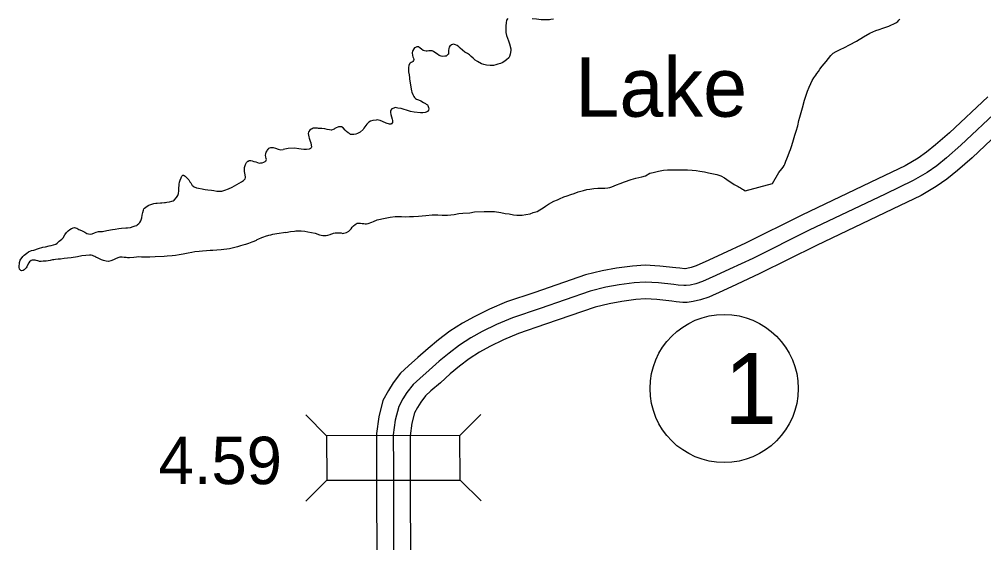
# Model space of a CAD drawing. Extents: x 31699 to 244310, y -8841 to 11474.
# Drawn here: x 101516 to 102088, y 3394 to 3705 of the extents above; entities that cross this region are included whole.
import ezdxf

# ---------------------------------------------------------------- set-up
doc = ezdxf.new("R2010")
doc.units = 0
for name, color, linetype in [('B_Logo', 7, 'Continuous'), ('R_Border Notes', 7, 'Continuous'), ('R_Draft', 7, 'Continuous'), ('R_XS_EARTHWORK_STAGE1', 7, 'Continuous'), ('R_XS_EARTHWORK_STAGE2', 7, 'Continuous'), ('S_WALL', 7, 'Continuous')]:
    doc.layers.add(name, color=color, linetype=linetype)

msp = doc.modelspace()

# ---------------------------------------------------------------- linework, layer by layer
at = {"layer": 'B_Logo'}
msp.add_lwpolyline([(102097.66, 3651.92), (102074.84, 3630.55), (102066.33, 3623.1), (102060.59, 3618.36), (102054.9, 3614.36), (102046.56, 3609.52), (102030, 3601.51), (101984.73, 3580.02), (101951.27, 3563.33), (101937.49, 3556.96), (101929.33, 3553.19), (101921.44, 3549.63), (101917.46, 3548.25), (101914.07, 3547.47), (101911.75, 3547.11), (101910.35, 3547.16), (101906.94, 3547.46), (101904.41, 3547.76), (101895.27, 3548.79), (101887.47, 3549.24), (101880.88, 3548.76), (101871.96, 3547.66), (101863.99, 3546.16), (101854.82, 3543.85), (101825.02, 3533.63), (101808.69, 3528.09), (101799.14, 3524.04), (101790.53, 3519.8), (101783.97, 3516.19), (101777.16, 3511.83), (101770.95, 3507.09), (101765, 3502.27), (101759.13, 3496.93), (101753.53, 3492.06), (101749.57, 3488.4), (101745.89, 3483.62), (101743.54, 3479.85), (101741.05, 3475.28), (101739.01, 3467.31), (101737.84, 3458.54), (101737.86, 3438.97), (101738, 3373.37)], dxfattribs=at)
at = {"layer": 'R_Border Notes'}
msp.add_circle((101934.29, 3486.01), 44, dxfattribs=at)
at = {"layer": 'R_Draft'}
for points in [[(101805.95, 3705.89), (101805.1, 3704.75), (101804.85, 3703.21), (101804.67, 3701.53), (101804.7, 3699.6), (101804.72, 3697.52), (101805.08, 3695.66), (101806.19, 3692.6), (101806.81, 3690.8), (101807.59, 3687.74), (101807.59, 3687), (101807.41, 3685.67), (101807.22, 3684.66), (101806.91, 3683.25), (101806.45, 3682.45), (101805, 3681.16), (101804.34, 3680.61), (101802.82, 3679.72), (101801.56, 3679.11), (101799.96, 3678.68), (101798.7, 3678.2), (101797.3, 3677.98), (101795.37, 3677.95), (101793.23, 3678.06), (101791.69, 3678.44), (101790.22, 3678.96), (101787.8, 3680.19), (101786.39, 3681.04), (101785.3, 3682.23), (101784.16, 3683.22), (101783.14, 3684.21), (101781.93, 3684.99), (101780.32, 3685.84), (101778.84, 3686.96), (101777.62, 3688.14), (101776.68, 3688.93), (101775.67, 3689.72), (101774.86, 3690.24), (101773.65, 3690.56), (101772.39, 3690.15), (101771.47, 3689.46), (101771.01, 3688.86), (101770.75, 3688.05), (101770.7, 3686.78), (101770.71, 3686.11), (101770.59, 3685.24), (101770.53, 3684.64), (101770.26, 3684.37), (101769.67, 3683.83), (101769.14, 3683.49), (101768.34, 3683.34), (101767.21, 3683.19), (101766.21, 3683.38), (101765.07, 3683.9), (101764.06, 3684.55), (101763.11, 3685.21), (101761.7, 3686.13), (101760.83, 3686.58), (101759.89, 3686.7), (101758.96, 3686.63), (101758.03, 3686.48), (101757.29, 3686.4), (101756.36, 3686.52), (101755.49, 3686.85), (101754.54, 3687.57), (101753.87, 3688.16), (101752.72, 3688.95)], [(101832.91, 3705.38), (101831.32, 3705.16), (101830.52, 3704.95), (101830.18, 3704.95), (101829.05, 3704.93), (101828.32, 3704.92), (101826.98, 3704.97), (101825.71, 3705.09), (101822.97, 3705.32), (101820.3, 3705.62)], [(101870.34, 3606.92), (101872.66, 3607.88), (101875.19, 3608.79), (101879.11, 3610.11), (101881.9, 3610.95), (101885.36, 3611.79), (101887.55, 3612.29), (101890.13, 3613.93), (101892.26, 3614.43), (101895.32, 3615.07), (101898.25, 3615.64), (101900.72, 3615.87), (101903.79, 3615.98), (101907.92, 3615.97), (101911.26, 3615.88), (101912.59, 3615.83), (101915.26, 3615.8), (101917.8, 3615.57), (101919.94, 3615.19), (101922.62, 3614.76), (101924.96, 3614.19), (101927.1, 3613.82), (101929.98, 3613.06), (101932.32, 3612.35), (101934.61, 3611.11), (101935.89, 3610.26), (101937.3, 3609.21), (101938.92, 3608.1), (101940.26, 3607.18), (101941.47, 3606.59), (101942.55, 3606.01), (101943.22, 3605.68), (101944.02, 3605.29), (101945.23, 3604.51), (101945.97, 3604.05), (101946.85, 3603.52), (101962.94, 3607.81), (101966.73, 3614.41), (101968.57, 3616.44), (101969.42, 3617.52), (101969.88, 3618.4), (101970.4, 3619.34), (101970.98, 3621.09), (101971.49, 3622.43), (101972.33, 3624.44), (101973.17, 3626.66), (101973.82, 3628.07), (101974.34, 3629.68), (101975.1, 3632.3), (101975.42, 3633.77), (101975.87, 3635.12), (101976.32, 3636.59), (101977.09, 3638.81), (101978.05, 3642.03), (101978.74, 3645.25), (101979.32, 3647.12), (101980.91, 3652.82), (101982.05, 3657.38), (101983.02, 3660.27), (101983.79, 3662.62), (101984.83, 3664.97), (101985.73, 3667.12), (101986.58, 3668.94), (101987.56, 3670.55), (101988.87, 3672.24), (101989.46, 3673.12), (101990.38, 3674.4), (101991.23, 3675.75), (101992.6, 3677.57), (101993.79, 3678.86), (101994.91, 3680.21), (101996.28, 3681.96), (101997.66, 3683.85), (101998.98, 3685.14), (102000.77, 3686.17), (102003.29, 3687.34), (102005.88, 3688.57), (102008.72, 3690.08), (102012.9, 3692.27), (102017.07, 3694.94), (102020.85, 3697.06), (102024.43, 3698.64), (102026.42, 3699.34), (102028.48, 3699.97), (102030.41, 3700.59), (102032.13, 3701.28), (102033.33, 3701.77), (102035.19, 3702.73), (102036.25, 3703.21), (102036.91, 3703.62), (102037.5, 3704.1), (102038.09, 3704.77), (102038.62, 3705.38)], [(101752.72, 3688.95), (101752.06, 3689.07), (101751.79, 3689.07), (101750.66, 3688.45), (101750.4, 3688.32), (101750, 3687.78), (101749.35, 3686.83), (101749.22, 3686.43), (101749.03, 3685.36), (101749.19, 3683.89), (101749.53, 3682.96), (101749.81, 3682.16), (101749.95, 3681.36), (101749.89, 3680.96), (101749.43, 3680.35), (101749.17, 3680.01), (101748.37, 3679.6), (101747.84, 3679.26), (101747.45, 3678.79), (101746.99, 3677.85), (101746.94, 3676.71), (101746.91, 3674.1), (101747.2, 3672.3), (101747.42, 3670.5), (101747.43, 3669.77), (101748.72, 3662.9), (101748.93, 3662.03), (101749.35, 3660.7), (101749.97, 3659.51), (101750.37, 3658.85), (101750.92, 3658.25), (101751.59, 3657.93), (101752.73, 3657.54), (101754.2, 3656.89), (101755.75, 3655.98), (101756.49, 3655.45), (101756.89, 3655.26), (101757.43, 3654.93), (101758.1, 3654.54), (101758.31, 3654.21), (101758.58, 3653.54), (101758.72, 3652.88), (101758.87, 3652.08), (101758.68, 3651.34), (101758.15, 3650.6), (101757.29, 3650.18), (101756.83, 3649.98), (101755.43, 3649.69), (101753.96, 3649.74), (101750.15, 3650.16), (101748.14, 3650.66), (101745.67, 3651.43), (101744.26, 3651.82), (101742.59, 3652.26), (101740.51, 3652.63), (101739.71, 3652.69), (101738.91, 3652.88), (101738.11, 3652.6), (101737.51, 3652.39), (101737.05, 3652.12), (101736.33, 3651.31), (101736.13, 3650.71), (101736.08, 3649.9), (101736.29, 3648.77), (101736.71, 3647.44), (101737.19, 3646.04), (101737.4, 3645.18), (101737.42, 3644.24), (101737.35, 3644.11), (101736.83, 3643.3), (101736.63, 3643.16), (101736.5, 3643.09), (101735.5, 3643.01), (101733.69, 3643.72), (101731.41, 3644.7), (101730.13, 3645.15), (101729.13, 3645.4), (101728.19, 3645.59), (101727.73, 3645.51), (101725.66, 3645.15), (101724.27, 3644.8), (101723.34, 3644.25), (101722.15, 3643.1), (101721.43, 3642.22), (101720.38, 3640.67), (101719.86, 3639.86), (101718.14, 3638.37), (101716.55, 3637.41), (101715.56, 3637.07), (101714.36, 3636.92), (101713.62, 3636.97), (101712.56, 3636.96), (101712.42, 3636.96), (101711.75, 3637.42), (101711.08, 3637.81), (101710.13, 3638.73), (101709.19, 3639.52), (101708.04, 3640.78), (101707.03, 3641.36), (101706.49, 3641.42), (101705.96, 3641.48)], [(101705.96, 3641.48), (101705.23, 3641.47), (101704.96, 3641.27), (101703.83, 3640.85), (101703.04, 3640.44), (101702.77, 3640.17), (101702.11, 3639.9), (101701.05, 3639.55), (101700.98, 3639.55), (101699.98, 3639.6), (101698.51, 3639.91), (101697.1, 3640.3), (101695.36, 3640.47), (101694.1, 3640.46), (101693.36, 3640.51), (101692.83, 3640.57), (101691.96, 3640.7), (101691.29, 3640.75), (101690.62, 3640.68), (101690.29, 3640.61), (101689.56, 3640.33), (101689.1, 3639.99), (101688.24, 3639.38), (101687.71, 3638.7), (101687.45, 3638.3), (101687.33, 3637.43), (101687.47, 3636.56), (101687.75, 3635.56), (101687.96, 3634.76), (101688.52, 3633.03), (101688.8, 3631.9), (101689.08, 3630.63), (101689.16, 3629.63), (101688.97, 3628.9), (101688.64, 3628.56), (101687.91, 3628.28), (101686.32, 3627.92), (101684.78, 3628.04), (101683.04, 3628.22), (101681.71, 3628.4), (101679.1, 3628.76), (101675.37, 3628.51), (101672.44, 3628.01)], [(101614.28, 3612.15), (101615.09, 3611.37), (101616.32, 3609.92), (101616.94, 3608.87), (101617.49, 3608.14), (101618.46, 3606.69), (101618.86, 3606.37), (101618.93, 3606.24), (101619.54, 3605.91), (101620.95, 3605.28), (101622.23, 3604.97), (101624.23, 3604.61), (101625.17, 3604.36), (101626.04, 3604.18), (101627.78, 3604.02), (101629.85, 3603.79), (101631.32, 3603.55), (101633.06, 3603.32), (101634.26, 3603.22), (101635.93, 3603.32), (101637.72, 3603.76), (101639.97, 3604.54), (101642.15, 3605.59), (101647.69, 3608.78), (101648.87, 3609.67), (101649.65, 3610.29), (101649.78, 3610.56), (101650.03, 3611.3), (101650.1, 3611.57), (101649.87, 3612.9), (101649.49, 3614.97), (101649.4, 3616.3), (101649.51, 3617.37), (101649.63, 3617.98), (101650.01, 3619.12), (101650.58, 3620.27), (101651.5, 3621.09), (101651.7, 3621.16), (101652.16, 3621.51), (101653.16, 3621.53), (101654.03, 3621.21), (101655.1, 3620.9), (101656.18, 3620.59), (101657.25, 3620.21), (101658.19, 3619.96), (101658.99, 3619.98), (101659.99, 3620.13), (101660.91, 3620.49), (101661.77, 3620.84), (101661.97, 3620.98), (101661.97, 3621.04), (101662.23, 3621.18), (101662.42, 3621.59), (101662.48, 3622.06), (101662.4, 3622.66), (101662.18, 3623.46), (101662.03, 3624.59), (101662.14, 3625.39), (101662.39, 3626.33), (101662.84, 3627.15), (101663.1, 3627.55), (101663.49, 3628.1), (101663.68, 3628.43), (101664.01, 3628.71), (101664.54, 3629.05), (101665.13, 3629.13), (101665.6, 3629.21), (101666.54, 3629.1), (101667.86, 3628.8), (101669.52, 3628.2), (101670.95, 3627.83), (101672.44, 3628.01)], [(101517.15, 3555.9), (101516.55, 3556.02), (101515.93, 3556.88), (101515.71, 3558.08), (101515.79, 3560.82), (101516.29, 3562.3), (101517.78, 3564.4), (101518.63, 3565.22), (101520.2, 3566.39), (101521.26, 3567.15), (101522.91, 3567.92), (101524.3, 3568.28), (101527.15, 3569.21), (101529.73, 3570), (101531.19, 3570.23), (101533.38, 3570.68), (101534.71, 3570.98), (101535.97, 3571.34), (101537.36, 3571.83), (101538.22, 3572.39), (101539.46, 3573.48), (101540.9, 3574.78), (101541.75, 3575.6), (101542.85, 3577.23), (101543.82, 3578.65), (101544.8, 3579.74), (101545.65, 3580.5), (101546.77, 3580.99), (101547.37, 3581.34), (101547.7, 3581.41), (101548.43, 3581.62), (101549.16, 3581.51), (101549.97, 3581.19), (101551.12, 3580.48), (101552.73, 3579.84), (101553.48, 3579.39), (101554.62, 3578.81), (101555.83, 3578.17), (101555.97, 3578.11), (101556.91, 3577.86), (101557.71, 3577.74), (101558.91, 3577.97), (101560.43, 3578.47), (101561.42, 3578.82), (101562.81, 3579.25), (101565.14, 3579.37), (101567.74, 3579.82), (101571.06, 3580.5), (101572.59, 3580.66), (101574.78, 3580.98), (101576.51, 3581.21), (101578.97, 3581.4), (101579.9, 3581.48), (101581.7, 3581.72), (101583.36, 3582.16), (101584.48, 3582.58), (101585.47, 3582.94), (101585.74, 3583.21), (101586.72, 3584.1), (101587.24, 3584.65), (101587.82, 3585.53), (101588.08, 3586.13), (101588.52, 3587.35), (101588.75, 3589.02), (101589.05, 3590.63), (101589.42, 3591.91), (101589.74, 3592.79), (101590, 3593.06), (101590.85, 3593.81), (101592.17, 3594.71), (101592.7, 3594.86), (101593.75, 3595.28), (101595.54, 3595.85), (101596.74, 3596.08), (101597.6, 3596.16), (101599.53, 3596.34), (101600.4, 3596.35), (101601.93, 3596.45), (101602.53, 3596.53), (101603.26, 3596.68), (101604.85, 3596.98), (101606.32, 3597.28), (101607.04, 3597.56), (101607.63, 3597.98), (101609.07, 3599.41), (101609.91, 3600.7), (101610.22, 3601.84), (101610.45, 3603.52), (101610.55, 3605.26), (101610.59, 3606.66), (101610.64, 3607.33), (101610.82, 3608.54), (101611.19, 3609.68), (101611.76, 3611.1), (101612.08, 3611.84), (101612.34, 3612.25), (101612.6, 3612.52), (101612.93, 3612.79), (101613.33, 3612.8), (101613.67, 3612.61), (101614.28, 3612.15)], [(101673.94, 3578.65), (101676.8, 3579.35), (101679.06, 3579.58), (101680, 3579.66), (101681.8, 3579.75), (101683.06, 3579.7), (101685.2, 3579.46), (101687.14, 3579.02), (101689.22, 3578.71), (101691.49, 3578.21), (101693.97, 3577.37), (101695.04, 3577.19), (101695.98, 3576.93), (101696.78, 3576.88), (101697.71, 3576.82), (101698.05, 3576.83), (101699.04, 3577.18), (101700.24, 3577.53), (101700.71, 3577.66), (101701.83, 3578.08), (101702.3, 3578.22), (101703.3, 3578.5), (101704.5, 3578.58), (101705.97, 3578.54), (101706.83, 3578.41), (101707.77, 3578.16), (101707.84, 3578.16), (101708.37, 3578.23), (101709.3, 3578.45), (101710.1, 3578.79), (101711.49, 3579.55), (101712.74, 3580.9), (101713.46, 3581.91), (101714.12, 3582.59), (101715.11, 3583.54), (101716.3, 3584.15), (101717.77, 3584.24), (101718.44, 3584.18), (101719.44, 3584.13), (101720.37, 3583.94), (101721.04, 3583.82), (101721.98, 3583.89), (101722.84, 3583.97), (101725.04, 3584.74), (101726.16, 3585.29), (101728.29, 3586.18), (101729.22, 3586.33), (101732.01, 3587.04), (101735.94, 3587.76), (101738.87, 3588.2), (101742.74, 3588.18), (101745.14, 3588.08), (101747.41, 3588.18), (101749.88, 3588.28), (101752.88, 3588.45), (101757.08, 3588.84), (101761.01, 3589.16), (101764.28, 3589.27), (101766.95, 3589.04), (101770.08, 3589.08), (101774.02, 3589.4), (101776.81, 3589.9), (101779.14, 3590.13), (101783.28, 3590.39), (101786.14, 3590.9), (101791.87, 3591.24), (101794.54, 3591.21), (101798.01, 3591.12), (101801.62, 3590.63), (101804.3, 3589.93), (101806.71, 3589.7), (101809.18, 3589.26), (101811.19, 3589.02), (101814.39, 3589), (101816.59, 3589.3), (101819.18, 3589.87), (101820.98, 3590.49), (101823.23, 3591.26), (101824.76, 3592.08), (101826.88, 3593.44), (101828.13, 3594.33), (101829.92, 3595.55), (101833.23, 3597.27), (101835.36, 3598.17), (101836.62, 3598.78), (101839.2, 3599.89), (101841, 3600.45), (101843.32, 3601.28), (101845.32, 3601.91), (101847.71, 3602.81), (101850.83, 3603.65), (101852.83, 3604.21), (101854.62, 3604.5), (101856.89, 3604.87), (101859.22, 3605.03), (101861.36, 3604.93), (101863.49, 3605.02), (101865.16, 3605.18), (101866.49, 3605.4), (101867.69, 3605.75), (101870.34, 3606.92)], [(101673.94, 3578.65), (101668.73, 3577.87), (101667.47, 3577.64), (101666.07, 3577.41), (101664.81, 3577.18), (101663.75, 3576.96), (101661.83, 3576.32), (101660.7, 3575.96), (101659.51, 3575.6), (101657.79, 3574.83), (101656.87, 3574.28), (101656.41, 3574), (101654.95, 3573.37), (101653.76, 3572.87), (101651.84, 3572.23), (101649.99, 3571.59), (101648.47, 3571.16), (101647.01, 3570.73), (101645.28, 3570.22), (101642.9, 3569.64), (101640.64, 3569.06), (101635.65, 3568.35), (101632.99, 3568.16), (101630.73, 3568.05), (101628.99, 3567.94), (101626.93, 3567.83), (101624.47, 3567.65), (101622.47, 3567.47), (101619.87, 3567.22), (101618.15, 3566.85), (101616.02, 3566.47), (101613.1, 3565.74), (101610.58, 3565.35), (101608.45, 3565.1), (101606.52, 3564.86), (101603.59, 3564.6), (101601.66, 3564.49), (101596.33, 3564.18), (101593.33, 3564.12), (101590.53, 3564.06), (101588.2, 3564.08), (101586.53, 3564.18), (101585.4, 3564.08), (101583.74, 3563.92), (101581.07, 3563.73), (101580.81, 3563.65), (101579.94, 3563.7), (101579.14, 3563.82), (101578, 3563.93), (101576.8, 3564.04), (101575.4, 3564.01), (101574.74, 3563.79), (101573.21, 3563.23), (101571.7, 3562.53), (101570.11, 3561.89), (101568.65, 3561.53), (101567.31, 3561.63), (101565.7, 3562.07), (101564.49, 3562.51), (101563.42, 3563.09), (101562.47, 3563.54), (101561.19, 3564.04), (101560.52, 3564.43), (101559.91, 3564.69), (101559.11, 3565.07), (101558.37, 3565.19), (101557.44, 3565.17), (101555.24, 3565.12), (101552.78, 3564.87), (101550.19, 3564.21), (101546.6, 3563.67), (101544.27, 3563.35), (101542.28, 3563.18), (101540.21, 3562.94), (101538.75, 3562.84), (101537.15, 3562.6), (101536.29, 3562.45), (101535.49, 3562.37), (101534.03, 3562.14), (101531.64, 3561.75), (101530.77, 3561.6), (101529.84, 3561.58), (101528.77, 3561.49), (101527.77, 3561.54), (101527.37, 3561.66), (101526.63, 3561.78), (101525.83, 3562.03), (101525.09, 3562.22), (101524.83, 3562.21), (101524.09, 3562.2), (101523.43, 3562.18), (101522.7, 3561.97), (101521.78, 3561.28), (101521.39, 3560.6), (101520.62, 3559.31), (101520.17, 3558.3), (101519.78, 3557.69), (101519.33, 3557.22), (101518.67, 3556.6), (101517.95, 3556.18), (101517.15, 3555.9)]]:
    msp.add_lwpolyline(points, dxfattribs=at)
at = {"layer": 'R_XS_EARTHWORK_STAGE1'}
for p, q in [((101698.24, 3457.99), (101685.79, 3470.43)), ((101777.44, 3458.07), (101789.88, 3470.53)), ((101698.27, 3431.59), (101685.84, 3419.14)), ((101777.47, 3431.67), (101789.93, 3419.24))]:
    msp.add_line(p, q, dxfattribs=at)
msp.add_lwpolyline([(101777.44, 3458.07), (101698.24, 3457.99), (101698.27, 3431.59), (101777.47, 3431.67)], close=True, dxfattribs=at)
at = {"layer": 'R_XS_EARTHWORK_STAGE2'}
for points in [[(102090.84, 3659.24), (102068.13, 3637.96), (102059.86, 3630.72), (102054.52, 3626.32), (102049.5, 3622.78), (102041.87, 3618.36), (102025.68, 3610.53), (101980.36, 3589.01), (101946.94, 3572.35), (101933.29, 3566.04), (101925.18, 3562.29), (101917.74, 3558.93), (101914.7, 3557.87), (101912.19, 3557.3), (101911.16, 3557.14), (101910.96, 3557.15), (101907.97, 3557.41), (101905.57, 3557.7), (101896.12, 3558.76), (101887.39, 3559.26), (101879.9, 3558.72), (101870.43, 3557.54), (101861.84, 3555.94), (101851.97, 3553.45), (101821.79, 3543.09), (101805.13, 3537.45), (101794.98, 3533.14), (101785.9, 3528.67), (101778.86, 3524.79), (101771.42, 3520.03), (101764.76, 3514.95), (101758.49, 3509.86), (101752.49, 3504.4), (101746.85, 3499.5), (101742.16, 3495.17), (101737.67, 3489.33), (101734.89, 3484.89), (101731.67, 3478.96), (101729.18, 3469.21), (101727.84, 3459.2), (101727.86, 3438.95), (101728, 3373.33)], [(102104.48, 3644.61), (102081.56, 3623.14), (102072.81, 3615.48), (102066.66, 3610.41), (102060.3, 3605.93), (102051.25, 3600.68), (102034.32, 3592.49), (101989.11, 3571.02), (101955.6, 3554.32), (101941.68, 3547.88), (101933.49, 3544.1), (101925.15, 3540.33), (101920.22, 3538.62), (101915.95, 3537.65), (101912.34, 3537.08), (101909.73, 3537.18), (101905.91, 3537.51), (101903.25, 3537.83), (101894.42, 3538.83), (101887.55, 3539.22), (101881.85, 3538.81), (101873.5, 3537.77), (101866.13, 3536.39), (101857.67, 3534.26), (101828.24, 3524.16), (101812.25, 3518.74), (101803.3, 3514.95), (101795.15, 3510.93), (101789.08, 3507.59), (101782.9, 3503.63), (101777.13, 3499.23), (101771.52, 3494.68), (101765.78, 3489.46), (101760.2, 3484.61), (101756.98, 3481.63), (101754.11, 3477.91), (101752.18, 3474.81), (101750.43, 3471.6), (101748.85, 3465.4), (101747.84, 3457.88), (101747.86, 3438.98), (101748, 3373.41)]]:
    msp.add_lwpolyline(points, dxfattribs=at)

# ---------------------------------------------------------------- texts
at = {"layer": 'R_Border Notes'}
msp.add_text('1', height=42.24, dxfattribs=at).set_placement((101934.29, 3464.89))
at = {"layer": 'R_Draft'}
msp.add_text('Lake', height=35.2, dxfattribs=at).set_placement((101845.93, 3647.46))
at = {"layer": 'S_WALL'}
msp.add_text('4.59', height=28.16, dxfattribs=at).set_placement((101598.4, 3429.2))

doc.saveas('drawing.dxf')
